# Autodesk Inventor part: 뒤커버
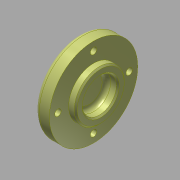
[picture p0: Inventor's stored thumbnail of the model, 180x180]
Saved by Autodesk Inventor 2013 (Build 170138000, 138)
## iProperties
Created: 2015-12
Part Number: 뒤커버
Document SubType Name: Modeling
Designer: mdu
Density: 2.71 g/cm^3
Material: 알루미늄 6061
Mass: 80.8084 g
Surface Area: 93.0376 cm^2
Volume: 29.8186 cm^3
Author: mdu
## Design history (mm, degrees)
sketch "스케치1"
  geometry: L1 (-7.5, 0)-(7.5, 0); L2 (-7.5, 0)-(-7.5, 31); L3 (-7.5, 31)-(2.5, 31); L4 (2.5, 31)-(2.5, 17.5); L5 (2.5, 17.5)-(7.5, 17.5); L6 (7.5, 17.5)-(7.5, 0); 2 further points
  constraints: 12 end point, 3 parallel, 1 coincident, 1 horizontal, 1 midpoint, 1 perpendicular
  dimensions: "d0" = 15 distance of L1.start L1.end; "d1" = 62 diameter of L3 L1; "d2" = 35 diameter of L5 L1; "d34" = 10 distance of L2.end L3.end
revolve "회전1" sketch "스케치1" stored, may be unused: angle "d6" = 90 deg
sketch "스케치2" dims "d32" = 50
  geometry: 3 further points
  constraints: 2 vertical alignment, 1 coincident, 2 other
hole "구멍1" sketch "스케치2" at (0, 25) diameter "d8" = 4.5; stored, may be unused: countersink angle "d12" = 90 deg, drill point angle "d14" = 118 deg; dims "d9" = 6, "d10" = 8, "d11" = 4.4, "d13" = 8
hole "구멍2" diameter "d20" = 24; stored, may be unused: countersink angle "d24" = 90 deg, drill point angle "d26" = 0 deg; dims "d18" = 10, "d19" = 10, "d21" = 6, "d22" = 8, "d23" = 4.4, "d25" = 8
fillet "모깎기1" dims "d27" = 3
fillet "모깎기2" dims "d28" = 3
chamfer "모따기1" distance "d29" = 1; stored, may be unused: second distance "d30" = 2, angle "d31" = 45 deg
node "솔리드1"
pattern_circular "원형 패턴1" dims angle "d16" = 360 deg
